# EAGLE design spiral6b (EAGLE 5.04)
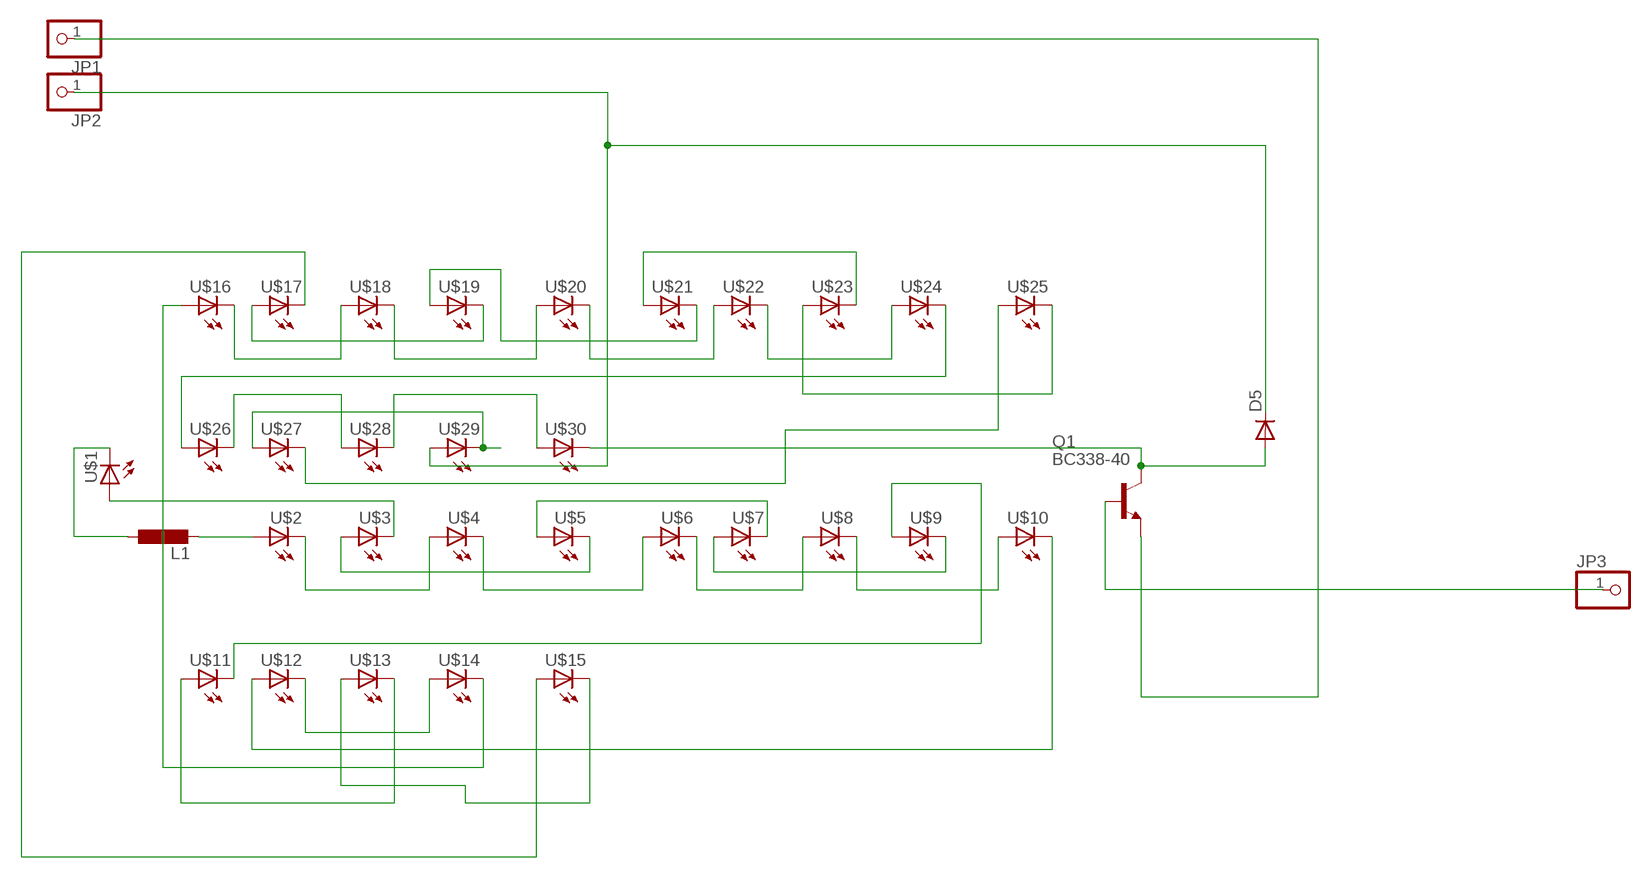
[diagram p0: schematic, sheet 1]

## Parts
D5  DIODE-D-2.5  [D-2.5]
JP1  PINHD-1X1  [1X01]
JP2  PINHD-1X1  [1X01]
JP3  PINHD-1X1  [1X01]
L1  L-EU0207/10  [0207/10]
Q1  BC338-40  [TO92-EBC]
U$1  LED5MM  [LED5MM]
U$2  LED5MM  [LED5MM]
U$3  LED5MM  [LED5MM]
U$4  LED5MM  [LED5MM]
U$5  LED5MM  [LED5MM]
U$6  LED5MM  [LED5MM]
U$7  LED5MM  [LED5MM]
U$8  LED5MM  [LED5MM]
U$9  LED5MM  [LED5MM]
U$10  LED5MM  [LED5MM]
U$11  LED5MM  [LED5MM]
U$12  LED5MM  [LED5MM]
U$13  LED5MM  [LED5MM]
U$14  LED5MM  [LED5MM]
U$15  LED5MM  [LED5MM]
U$16  LED5MM  [LED5MM]
U$17  LED5MM  [LED5MM]
U$18  LED5MM  [LED5MM]
U$19  LED5MM  [LED5MM]
U$20  LED5MM  [LED5MM]
U$21  LED5MM  [LED5MM]
U$22  LED5MM  [LED5MM]
U$23  LED5MM  [LED5MM]
U$24  LED5MM  [LED5MM]
U$25  LED5MM  [LED5MM]
U$26  LED5MM  [LED5MM]
U$27  LED5MM  [LED5MM]
U$28  LED5MM  [LED5MM]
U$29  LED5MM  [LED5MM]
U$30  LED5MM  [LED5MM]

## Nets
N$1: JP1.1 Q1.E
N$2: U$2.K(C) U$4.A
N$3: U$4.K(C) U$6.A
N$4: U$6.K(C) U$8.A
N$5: U$8.K(C) U$10.A
N$6: U$1.A U$3.K(C)
N$7: U$3.A U$5.K(C)
N$8: U$5.A U$7.K(C)
N$9: U$7.A U$9.K(C)
N$10: U$10.K(C) U$12.A
N$11: U$12.K(C) U$14.A
N$12: U$14.K(C) U$16.A
N$13: U$16.K(C) U$18.A
N$14: U$18.K(C) U$20.A
N$15: U$20.K(C) U$22.A
N$16: U$22.K(C) U$24.A
N$17: U$24.K(C) U$26.A
N$18: U$26.K(C) U$28.A
N$19: U$28.K(C) U$30.A
N$21: L1.2 U$2.A
N$22: L1.1 U$1.K(C)
N$23: U$27.A U$29.K(C)
N$24: U$25.A U$27.K(C)
N$27: U$9.A U$11.K(C)
N$29: U$11.A U$13.K(C)
N$30: U$13.A U$15.K(C)
N$31: U$15.A U$17.K(C)
N$32: U$17.A U$19.K(C)
N$33: U$19.A U$21.K(C)
N$34: U$21.A U$23.K(C)
N$35: U$23.A U$25.K(C)
N$36: D5.A Q1.C U$30.K(C)
N$40: JP3.1 Q1.B
V300: D5.C JP2.1 U$29.A

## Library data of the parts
D5 = diode-1:DIODE-: DIODE
JP1-JP3 = pinhead:PINHD-1X1: PIN HEADER
L1 = rcl-2:L-EU: INDUCTOR, European symbol
Q1 = transistor-npn:BC338*: NPN Transistor
U$1-U$30 = led(2):LED: LED

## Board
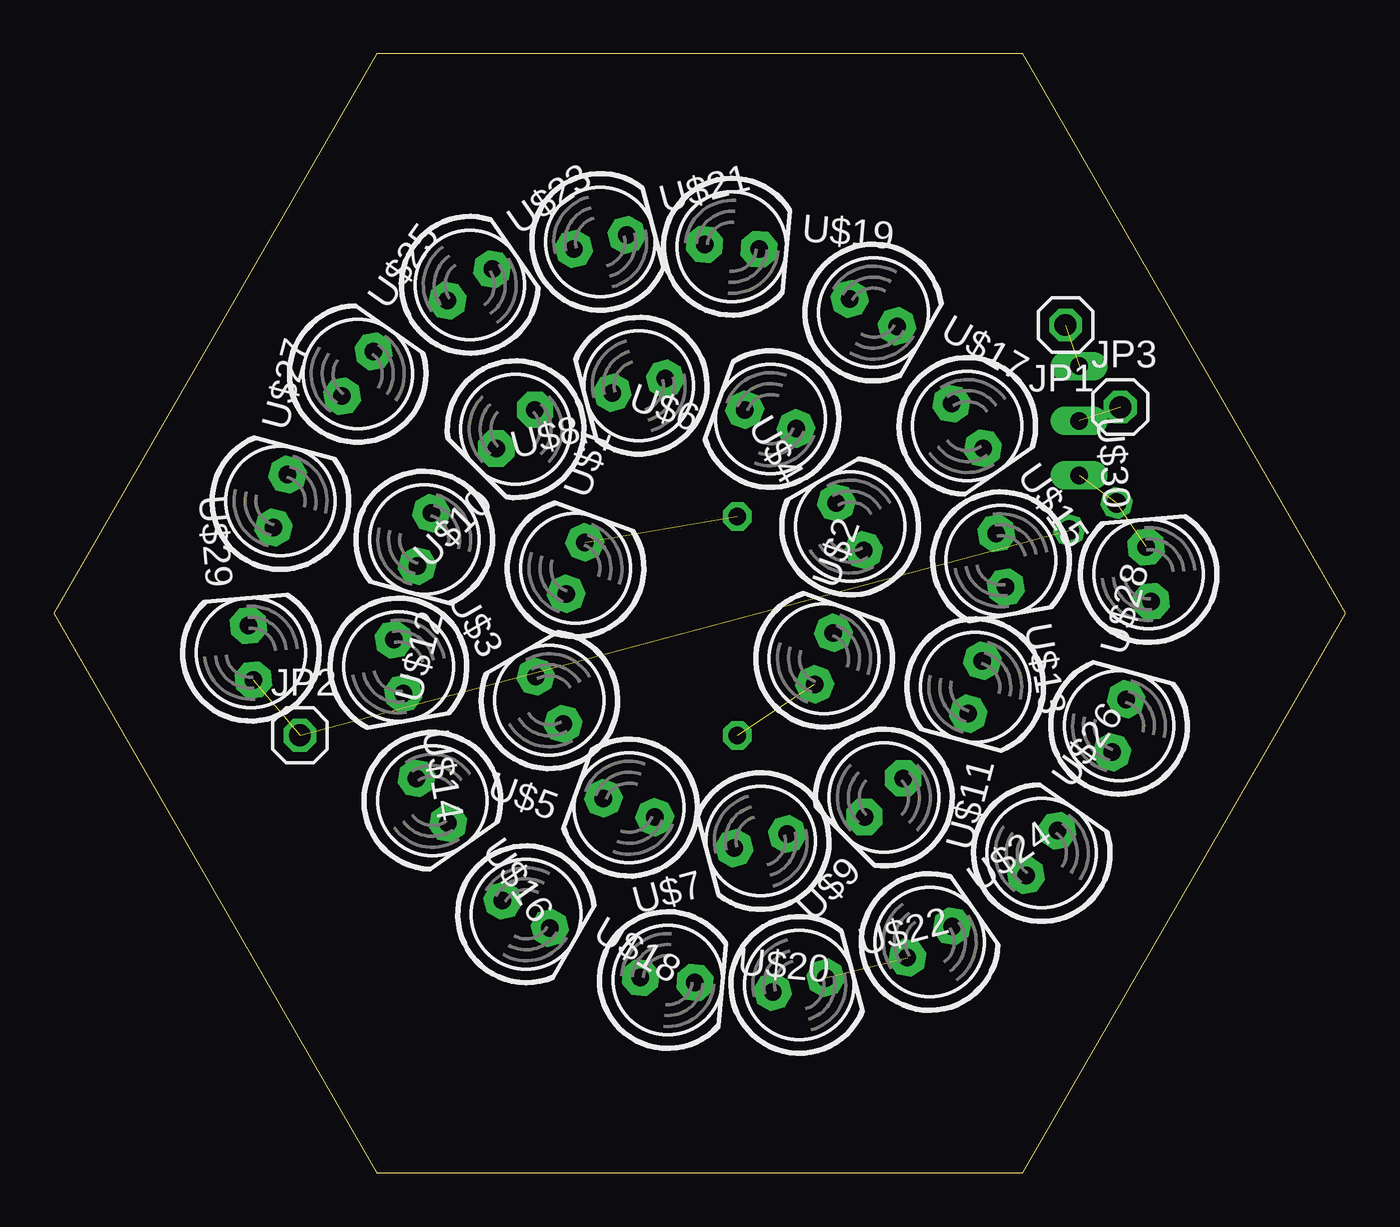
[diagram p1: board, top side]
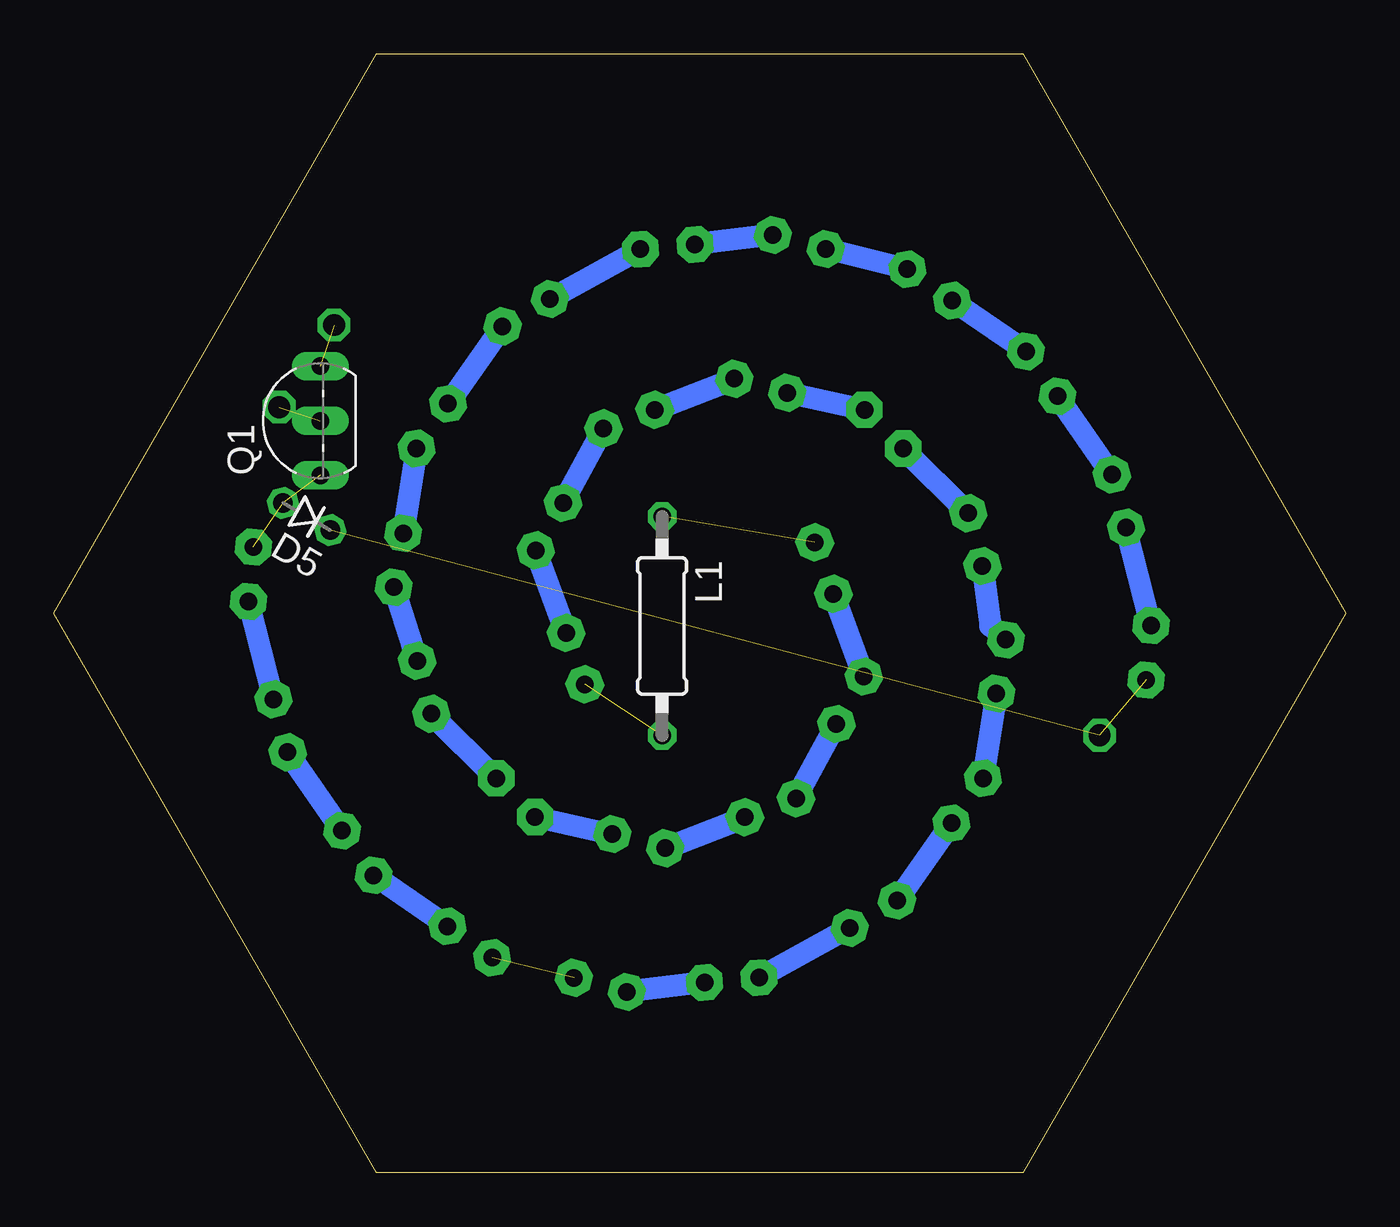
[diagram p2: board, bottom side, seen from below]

Size 60 x 51.96 mm. Coordinates in mm from the lower left corner, seen from the top.
Outline: 15,0 45,0 60,25.98 45,51.96 15,51.96 0,25.98 15,0
Copper layers (1*16): Top 0.035mm / dielectric 1.5mm / Bottom 0.035mm
Design rules "default": minimum track width 10mil, minimum drill 24mil, track to track 8mil, track to pad 8mil, pad to pad 8mil, via to via 8mil, smd to smd 8mil, copper to edge 40mil, drill to drill 8mil, minimum pad ring 10mil, minimum via ring 8mil, stop-mask expansion 4mil, vias tented up to drill 0mil, thermal gap 10mil

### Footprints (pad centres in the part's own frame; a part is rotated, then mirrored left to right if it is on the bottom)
D-2.5 = drill 0.9 octagon: A 1.27,0; C -1.27,0
1X01 = drill 1.016 octagon: 1 0,0
0207/10 = drill 0.813 octagon: 1 -5.08,0; 2 5.08,0
TO92-EBC = drill 0.813 long: B 0,-1.27; C -2.54,-1.27; E 2.54,-1.27
LED5MM = drill 0.813 pad 1.676 octagon: A -1.27,0; K 1.27,0

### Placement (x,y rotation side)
D5  48.26,30.48 150 bottom
JP1  46.99,39.37 180 top
JP2  11.43,20.32 0 top
JP3  49.53,35.56 0 top
L1  31.75,25.4 270 bottom
Q1  48.9,34.92 90 bottom
U$1  24.23,28.08 70 top
U$2  35.77,23.88 70 top
U$3  23.02,21.95 120 top
U$4  36.98,30.01 120 top
U$5  26.72,16.96 160 top
U$6  33.28,35 160 top
U$7  32.83,15.41 195 top
U$8  27.17,36.55 195 top
U$9  38.55,17.43 225 top
U$10  21.45,34.53 225 top
U$11  42.8,22.55 255 top
U$12  17.2,29.41 255 top
U$13  43.99,28.45 280 top
U$14  16.01,23.51 280 top
U$15  42.42,34.68 305 top
U$16  17.58,17.28 305 top
U$17  38.06,39.95 330 top
U$18  21.94,12.01 330 top
U$19  31.49,43 355 top
U$20  28.51,8.96 355 top
U$21  25.38,43.23 14.9 top
U$22  34.62,8.73 14.9 top
U$23  19.32,41.23 35 top
U$24  40.68,10.73 35 top
U$25  14.12,37.1 54.9 top
U$26  45.88,14.86 54.9 top
U$27  10.53,31.2 75 top
U$28  49.47,20.76 75 top
U$29  9.15,24.16 95 top
U$30  50.85,27.8 95 top

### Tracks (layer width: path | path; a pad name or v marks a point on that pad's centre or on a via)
N$1  (1 unrouted)
N$2
  Bottom 1.016: U$2.K U$4.A
N$3
  Bottom 1.016: U$4.K U$6.A
N$4
  Bottom 1.016: U$6.K U$8.A
N$5
  Bottom 1.016: U$8.K U$10.A
N$6
  Bottom 1.016: U$3.K U$1.A
N$7
  Bottom 1.016: U$5.K U$3.A
N$8
  Bottom 1.016: U$7.K U$5.A
N$9
  Bottom 1.016: U$9.K U$7.A
N$10
  Bottom 1.016: U$10.K U$12.A
N$11
  Bottom 1.016: U$12.K 16.51,25.4 U$14.A
N$12
  Bottom 1.016: U$14.K U$16.A
N$13
  Bottom 1.016: U$16.K U$18.A
N$14
  Bottom 1.016: U$18.K U$20.A
N$15
  Bottom 1.016: U$20.K U$22.A
N$16  (1 unrouted)
N$17
  Bottom 1.016: U$24.K U$26.A
N$18
  Bottom 1.016: U$26.K U$28.A
N$19
  Bottom 1.016: U$28.K U$30.A
N$21  (1 unrouted)
N$22  (1 unrouted)
N$23
  Bottom 1.016: U$29.K U$27.A
N$24
  Bottom 1.016: U$27.K U$25.A
N$27
  Bottom 1.016: U$11.K U$9.A
N$29
  Bottom 1.016: U$13.K U$11.A
N$30
  Bottom 1.016: U$15.K U$13.A
N$31
  Bottom 1.016: U$17.K U$15.A
N$32
  Bottom 1.016: U$19.K 36.83,40.64 U$17.A
N$33
  Bottom 1.016: U$21.K U$19.A
N$34
  Bottom 1.016: U$23.K U$21.A
N$35
  Bottom 1.016: U$25.K U$23.A
N$36  (2 unrouted)
N$40  (1 unrouted)
V300  (2 unrouted)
